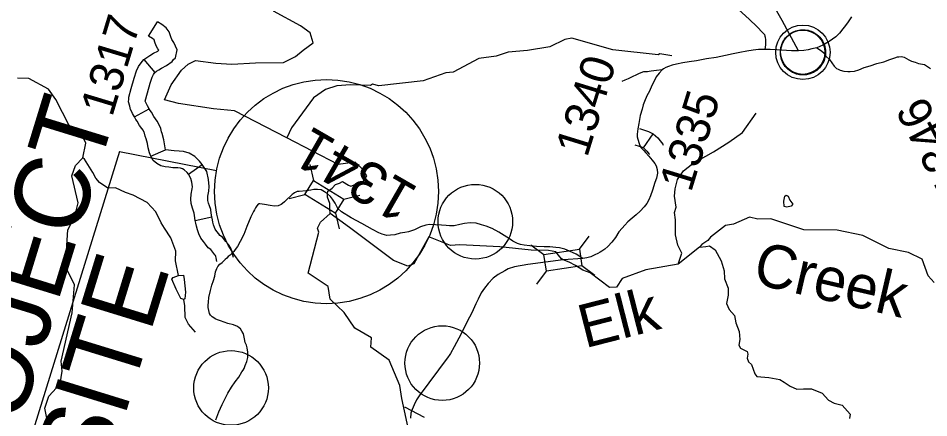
# Model space of a CAD drawing. Extents: x 1347947 to 1350662, y 1027710 to 1030532.
# Drawn here: x 1348130.6 to 1348252.2, y 1028877.9 to 1028931.2 of the extents above; entities that cross this region are included whole.
import ezdxf

# ---------------------------------------------------------------- set-up
doc = ezdxf.new("R2010")
doc.units = 0
for name, color, linetype in [('Default', 7, 'Continuous'), ('Prop Leader Line Light', 7, 'Continuous'), ('Prop Leader Line Medium', 7, 'Continuous'), ('Sheet Data Field CELL', 7, 'Continuous')]:
    doc.layers.add(name, color=color, linetype=linetype)

msp = doc.modelspace()

# ---------------------------------------------------------------- linework, layer by layer
at = {"layer": 'Default'}
for p, q in [((1348147.96, 1028928.84), (1348149.17, 1028930.74)), ((1348147.36, 1028925.69), (1348148.82, 1028923.97)), ((1348146.1, 1028918.05), (1348148.07, 1028919.14)), ((1348214.08, 1028913.91), (1348215.35, 1028915.8)), ((1348148.28, 1028912.8), (1348150.23, 1028913.64)), ((1348153.3, 1028910.4), (1348155.12, 1028911.72)), ((1348169.51, 1028911.7), (1348170.02, 1028909.58)), ((1348166.74, 1028907.17), (1348168.86, 1028907.68)), ((1348174.08, 1028907.08), (1348176.2, 1028907.59)), ((1348154.22, 1028904.25), (1348156.43, 1028904.7)), ((1348172.94, 1028905.22), (1348173.45, 1028903.11)), ((1348205.51, 1028900.39), (1348206.81, 1028902.14)), ((1348199.04, 1028900.99), (1348200.79, 1028899.69)), ((1348199.83, 1028895.74), (1348201.13, 1028897.49)), ((1348205.83, 1028898.24), (1348207.59, 1028896.94))]:
    msp.add_line(p, q, dxfattribs=at)
for points in [[(1348226.24, 1028932.88), (1348228.24, 1028931.02), (1348229.22, 1028930.12), (1348230.03, 1028929.25), (1348230.23, 1028929.03), (1348230.29, 1028928.82), (1348230.32, 1028928.7), (1348230.35, 1028928.33), (1348230.35, 1028927.65), (1348230.26, 1028927.04)], [(1348234.8, 1028926.88), (1348232.58, 1028930.89), (1348231.37, 1028933.07)], [(1348166.44, 1028915.24), (1348159.45, 1028918.86), (1348156.67, 1028919.11), (1348151.99, 1028919.83), (1348150.12, 1028920.32), (1348150.98, 1028922.32), (1348152.37, 1028924.29), (1348153.25, 1028925.09), (1348154.25, 1028925.58), (1348156.95, 1028925.21), (1348159.11, 1028925.08), (1348162.27, 1028925.27), (1348166, 1028925.3), (1348167.6, 1028926.11), (1348168.62, 1028926.97), (1348169.96, 1028927.94), (1348169.56, 1028929.26), (1348168.29, 1028930.21), (1348164.67, 1028932.15)], [(1348241.85, 1028931.38), (1348241.39, 1028930.73), (1348241.04, 1028930.24), (1348240.71, 1028929.79), (1348240.26, 1028929.22), (1348239.76, 1028928.73), (1348238.89, 1028928.09), (1348238.03, 1028927.63), (1348237.21, 1028927.25)], [(1348159.31, 1028899.29), (1348159.2, 1028899.76), (1348159.13, 1028900.06), (1348158.95, 1028900.56), (1348158.66, 1028901.02), (1348158.31, 1028901.43), (1348157.85, 1028902.01), (1348157.52, 1028902.25), (1348157.35, 1028902.45), (1348157.12, 1028902.77), (1348156.88, 1028903.08), (1348156.78, 1028903.28), (1348156.67, 1028903.65), (1348156.57, 1028904), (1348156.52, 1028904.3), (1348156.43, 1028904.7), (1348156.33, 1028905.21), (1348156.29, 1028905.68), (1348156.1, 1028906.2), (1348156, 1028906.53), (1348155.9, 1028906.88), (1348155.89, 1028907.09), (1348155.91, 1028907.46), (1348156.05, 1028908.13), (1348156.09, 1028908.76), (1348156, 1028909.72), (1348155.75, 1028910.75), (1348155.12, 1028911.72), (1348154.79, 1028912.13), (1348154.15, 1028912.77), (1348153.41, 1028913.23), (1348152.66, 1028913.42), (1348152.05, 1028913.49), (1348151.39, 1028913.52), (1348150.23, 1028913.64), (1348150.04, 1028915.01), (1348149.78, 1028915.84), (1348149.7, 1028916.06), (1348149.62, 1028916.49), (1348149.42, 1028916.99), (1348149.12, 1028917.49), (1348148.9, 1028917.8), (1348148.69, 1028918.1), (1348148.36, 1028918.69), (1348148.21, 1028918.9), (1348148.07, 1028919.14), (1348147.86, 1028919.54), (1348147.77, 1028919.72), (1348147.55, 1028920.16), (1348147.84, 1028921.25), (1348148.2, 1028922.54), (1348148.48, 1028923.36), (1348148.63, 1028923.69), (1348148.82, 1028923.97), (1348149.05, 1028924.14), (1348149.34, 1028924.35), (1348149.72, 1028924.55), (1348150.4, 1028924.92), (1348151.12, 1028925.44), (1348151.32, 1028925.69), (1348151.57, 1028925.94), (1348151.79, 1028926.99), (1348151.36, 1028927.97), (1348151.08, 1028928.36), (1348150.96, 1028928.72), (1348150.75, 1028929.38), (1348150.33, 1028929.94), (1348149.77, 1028930.36), (1348149.17, 1028930.74)], [(1348157.12, 1028898.78), (1348157.01, 1028899.24), (1348156.97, 1028899.42), (1348156.92, 1028899.56), (1348156.85, 1028899.67), (1348156.57, 1028900), (1348156.28, 1028900.37), (1348155.95, 1028900.6), (1348155.58, 1028901.07), (1348155.31, 1028901.42), (1348154.96, 1028901.89), (1348154.68, 1028902.45), (1348154.51, 1028903.01), (1348154.37, 1028903.49), (1348154.31, 1028903.86), (1348154.22, 1028904.25), (1348154.1, 1028904.91), (1348154.08, 1028905.2), (1348153.97, 1028905.47), (1348153.85, 1028905.87), (1348153.66, 1028906.51), (1348153.63, 1028907.1), (1348153.67, 1028907.76), (1348153.82, 1028908.45), (1348153.84, 1028908.73), (1348153.78, 1028909.34), (1348153.65, 1028909.85), (1348153.3, 1028910.4), (1348153.12, 1028910.62), (1348152.73, 1028911), (1348152.52, 1028911.14), (1348152.26, 1028911.2), (1348151.87, 1028911.25), (1348151.23, 1028911.27), (1348150.68, 1028911.33), (1348150.21, 1028911.4), (1348149.62, 1028911.52), (1348149.08, 1028911.85), (1348148.61, 1028912.25), (1348148.28, 1028912.8), (1348148.09, 1028913.27), (1348147.92, 1028913.94), (1348147.84, 1028914.52), (1348147.65, 1028915.13), (1348147.52, 1028915.48), (1348147.45, 1028915.86), (1348147.4, 1028915.99), (1348147.24, 1028916.27), (1348147.07, 1028916.5), (1348146.79, 1028916.89), (1348146.45, 1028917.49), (1348146.3, 1028917.7), (1348146.1, 1028918.05), (1348145.85, 1028918.52), (1348145.75, 1028918.73), (1348145.59, 1028919.05), (1348145.47, 1028919.47), (1348145.31, 1028920.05), (1348145.35, 1028920.41), (1348145.37, 1028920.69), (1348145.67, 1028921.83), (1348146.04, 1028923.21), (1348146.39, 1028924.21), (1348146.66, 1028924.79), (1348146.99, 1028925.28), (1348147.36, 1028925.69), (1348147.74, 1028925.97), (1348148.16, 1028926.26), (1348148.65, 1028926.53), (1348149.2, 1028926.82), (1348149.34, 1028926.93), (1348149.2, 1028927.12), (1348148.98, 1028927.53), (1348148.82, 1028928.04), (1348148.73, 1028928.33), (1348148.49, 1028928.5), (1348147.96, 1028928.84)], [(1348217.85, 1028926.18), (1348216.24, 1028926.48), (1348216.02, 1028926.31), (1348209.97, 1028926.99), (1348204.5, 1028928.56), (1348203.57, 1028928.37), (1348201.55, 1028927.38), (1348198.57, 1028926.89), (1348196.02, 1028926.68), (1348194.4, 1028926.15), (1348192.09, 1028925.85), (1348188.64, 1028924), (1348187.67, 1028923.92), (1348184.66, 1028922.84), (1348178.72, 1028922.2), (1348177.89, 1028922.41), (1348177.63, 1028922.25), (1348174.95, 1028922.33), (1348173.14, 1028922.2), (1348171.6, 1028921.72), (1348170, 1028920.59), (1348167.07, 1028916.59), (1348166.44, 1028915.24)], [(1348230.26, 1028927.04), (1348229.44, 1028927.02), (1348228.74, 1028926.93), (1348227.88, 1028926.8), (1348226.96, 1028926.63), (1348226.06, 1028926.44), (1348225.03, 1028926.23), (1348223.79, 1028925.99), (1348222.51, 1028925.78), (1348221.14, 1028925.54), (1348220.16, 1028925.4), (1348219.33, 1028925.24), (1348218.5, 1028925.08), (1348217.9, 1028924.96), (1348217.4, 1028924.79), (1348217.05, 1028924.66), (1348216.74, 1028924.48), (1348216.57, 1028924.34)], [(1348234.8, 1028926.88), (1348233.83, 1028926.85), (1348231.88, 1028926.98), (1348231, 1028927.04), (1348230.26, 1028927.04)], [(1348237.21, 1028927.25), (1348236.55, 1028927.11), (1348236.08, 1028927.01), (1348235.5, 1028926.9), (1348234.8, 1028926.88)], [(1348237.21, 1028927.25), (1348237.87, 1028926.85), (1348238.19, 1028926.53), (1348238.45, 1028926.16), (1348238.91, 1028925.69), (1348239.21, 1028925.27), (1348239.54, 1028924.82), (1348239.85, 1028924.51), (1348240.06, 1028924.41), (1348240.35, 1028924.29), (1348240.82, 1028924.17), (1348241.38, 1028924.12), (1348241.68, 1028924.11), (1348242.25, 1028924.14), (1348242.82, 1028924.33), (1348243.56, 1028924.63), (1348244.34, 1028924.88), (1348245.26, 1028925.16), (1348246.16, 1028925.41), (1348246.97, 1028925.72), (1348247.66, 1028925.95), (1348248, 1028926.04), (1348248.17, 1028926.07), (1348248.52, 1028926.11), (1348248.87, 1028926.01), (1348249.2, 1028925.85), (1348249.52, 1028925.64), (1348249.86, 1028925.48), (1348250.38, 1028925.33), (1348250.8, 1028925.18), (1348251.59, 1028925.02), (1348252.41, 1028924.5)], [(1348216.57, 1028924.34), (1348215.8, 1028924.24), (1348215.11, 1028924.13), (1348214.84, 1028924.11), (1348214.62, 1028924.08), (1348214.09, 1028924.04), (1348213.51, 1028923.86), (1348213.14, 1028923.64), (1348212.55, 1028923.39), (1348212.01, 1028923.13), (1348211.6, 1028922.95), (1348211.19, 1028922.77)], [(1348216.57, 1028924.34), (1348216.19, 1028923.89), (1348215.79, 1028923.38), (1348215.53, 1028922.91), (1348215.2, 1028922.23), (1348214.88, 1028921.47), (1348214.54, 1028920.86), (1348214.21, 1028920.12), (1348214.04, 1028919.65), (1348213.89, 1028919.08), (1348213.63, 1028918.23), (1348213.44, 1028917.15), (1348213.32, 1028916.44), (1348213.24, 1028915.76), (1348213.23, 1028915.41)], [(1348134.7, 1028876.27), (1348134.12, 1028879.19), (1348134.68, 1028880.8), (1348136.17, 1028882.45), (1348136.43, 1028884.15), (1348136.32, 1028885.46), (1348137.8, 1028891.92), (1348138.09, 1028895.64), (1348136.9, 1028898.1), (1348137.18, 1028903.01), (1348138.13, 1028904.8), (1348138.59, 1028906.59), (1348137.74, 1028910.21), (1348138.21, 1028911.57), (1348139.2, 1028912.6), (1348139.62, 1028914.56), (1348139.01, 1028915.79), (1348137.36, 1028916.89), (1348135.6, 1028920.38), (1348134.63, 1028921.75), (1348131.99, 1028923.18), (1348130.49, 1028923.2)], [(1348218.69, 1028898.43), (1348219.19, 1028899.87), (1348218.67, 1028900.93), (1348218.34, 1028902.31), (1348218.34, 1028904.31), (1348218.22, 1028905.31), (1348218.46, 1028906), (1348218.22, 1028907.47), (1348218.31, 1028908.46), (1348218.64, 1028909.71), (1348219.43, 1028910.86), (1348220.65, 1028911.82), (1348223.44, 1028913.39), (1348225.47, 1028914.66), (1348227.32, 1028915.97), (1348229.12, 1028918.56)], [(1348213.23, 1028915.41), (1348213.46, 1028914.64), (1348213.54, 1028914.35), (1348213.74, 1028913.99), (1348214.11, 1028913.58), (1348214.38, 1028913.26), (1348214.77, 1028912.83), (1348215.25, 1028912.3), (1348215.59, 1028911.84), (1348215.76, 1028911.51), (1348215.89, 1028911.03), (1348215.93, 1028910.54), (1348215.8, 1028909.87), (1348215.57, 1028909.3), (1348215.26, 1028908.29), (1348215, 1028907.54), (1348214.8, 1028907), (1348214.52, 1028906.49), (1348214.18, 1028906.05), (1348213.64, 1028905.49), (1348213.11, 1028904.98), (1348212.56, 1028904.56), (1348212, 1028904.06), (1348211.58, 1028903.6), (1348211.22, 1028903.23), (1348210.8, 1028902.73), (1348210.35, 1028901.98), (1348209.84, 1028901.35), (1348209.3, 1028900.75), (1348208.92, 1028900.41), (1348208.5, 1028900.16), (1348208.28, 1028900.03), (1348207.98, 1028899.83), (1348207.57, 1028899.67), (1348207.31, 1028899.53), (1348207.04, 1028899.4), (1348206.53, 1028899.27), (1348205.96, 1028899.16)], [(1348213.53, 1028916.49), (1348214.23, 1028916.3), (1348214.73, 1028916.1), (1348215.35, 1028915.8), (1348215.98, 1028915.24), (1348216.29, 1028914.85), (1348216.64, 1028914.4), (1348216.71, 1028914.3)], [(1348171.86, 1028907.78), (1348171.94, 1028908.13), (1348172.49, 1028908.55), (1348172.96, 1028909.03), (1348173.48, 1028909.23), (1348173.88, 1028909.42), (1348174.68, 1028908.95), (1348174.98, 1028908.83), (1348176.68, 1028909.47), (1348177.12, 1028910.18), (1348176.55, 1028911.07), (1348175.57, 1028912), (1348173.31, 1028911.72), (1348166.44, 1028915.24)], [(1348212.93, 1028914.32), (1348213.51, 1028914.16), (1348213.82, 1028914.04), (1348214.08, 1028913.91), (1348214.35, 1028913.67), (1348214.52, 1028913.46), (1348214.82, 1028913.08), (1348214.85, 1028913.02)], [(1348150.97, 1028901.93), (1348150.12, 1028903.19), (1348149.68, 1028903.91), (1348148.94, 1028905.41), (1348147.78, 1028906.64), (1348145.93, 1028907.59), (1348144.92, 1028907.95), (1348143.57, 1028908.58), (1348142.53, 1028908.54), (1348141.41, 1028909.3), (1348140.96, 1028909.86), (1348140.56, 1028910.64), (1348139.44, 1028912.41), (1348139.2, 1028912.6)], [(1348171.86, 1028907.78), (1348171.47, 1028908.06), (1348171.05, 1028908.32), (1348170.53, 1028908.38), (1348170.06, 1028908.36), (1348169.66, 1028908.28), (1348169.02, 1028908.21), (1348168.11, 1028908.12), (1348167.82, 1028908.1), (1348167.48, 1028907.91), (1348167.31, 1028907.81), (1348167.16, 1028907.68), (1348166.92, 1028907.46), (1348166.55, 1028907.13), (1348166.14, 1028906.72), (1348165.89, 1028906.51), (1348165.7, 1028906.36), (1348165.29, 1028906.17), (1348164.79, 1028906.16), (1348164.23, 1028906.24), (1348163.47, 1028906.36), (1348162.86, 1028906.45), (1348162.73, 1028906.45), (1348162.62, 1028906.4), (1348162.46, 1028906.18), (1348162.28, 1028905.92), (1348162.11, 1028905.64), (1348161.98, 1028905.44), (1348161.65, 1028904.72), (1348161.12, 1028903.44), (1348160.71, 1028902.35), (1348160.23, 1028901.41), (1348159.87, 1028900.78), (1348159.57, 1028900.35), (1348159.35, 1028900.11), (1348158.86, 1028899.63), (1348158.63, 1028899.42), (1348158.42, 1028899.2), (1348158.22, 1028899.03)], [(1348172.25, 1028905.18), (1348172.19, 1028905.79), (1348172.19, 1028906.51), (1348171.87, 1028907.35), (1348171.86, 1028907.78)], [(1348205.96, 1028899.16), (1348205.07, 1028899.76), (1348204.18, 1028900.16), (1348203.57, 1028900.42), (1348202.85, 1028900.58), (1348202.38, 1028900.62), (1348201.55, 1028900.72), (1348200.8, 1028900.7), (1348199.78, 1028900.76), (1348198.92, 1028900.85), (1348198.15, 1028900.95), (1348197.66, 1028901.01), (1348197.26, 1028901.15), (1348196.65, 1028901.48), (1348196.2, 1028901.78), (1348195.49, 1028902.24), (1348194.76, 1028902.69), (1348193.87, 1028903.18), (1348193.08, 1028903.48), (1348192.45, 1028903.66), (1348191.72, 1028903.86), (1348190.91, 1028903.92), (1348190.16, 1028903.84), (1348189.53, 1028903.68), (1348188.78, 1028903.54), (1348188.16, 1028903.51), (1348187.71, 1028903.55), (1348187.1, 1028903.59), (1348186.28, 1028903.64), (1348185.5, 1028903.72), (1348184.99, 1028903.59), (1348184.31, 1028903.4), (1348183.51, 1028903.01), (1348182.68, 1028902.74), (1348182.2, 1028902.62), (1348181.6, 1028902.55), (1348180.85, 1028902.31), (1348180.31, 1028902.26), (1348179.81, 1028902.21), (1348179.2, 1028902.39), (1348178.74, 1028902.61), (1348177.87, 1028903.03), (1348176.46, 1028903.83), (1348175.03, 1028904.61), (1348173.75, 1028905.39), (1348173.26, 1028905.85), (1348172.92, 1028906.54), (1348172.56, 1028907.1), (1348172.26, 1028907.45), (1348171.86, 1028907.78)], [(1348233.78, 1028906.16), (1348233.23, 1028905.99), (1348232.87, 1028906.11), (1348232.84, 1028906.8), (1348232.97, 1028907.46), (1348233.13, 1028907.61), (1348233.38, 1028907.46), (1348233.6, 1028906.94), (1348234.03, 1028906.42), (1348233.78, 1028906.16)], [(1348181.17, 1028864.6), (1348181.41, 1028868.13), (1348182.01, 1028870.15), (1348183.11, 1028874.69), (1348182.5, 1028877.18), (1348181.79, 1028880.51), (1348181.55, 1028882.21), (1348180.13, 1028885.6), (1348177.67, 1028887.36), (1348177.77, 1028888.57), (1348175.54, 1028889.88), (1348174.09, 1028891.94), (1348172.25, 1028893.72), (1348171.98, 1028895.42), (1348169.29, 1028897.21), (1348170.72, 1028902.66), (1348170.54, 1028903.22), (1348170.93, 1028904.03), (1348172.25, 1028905.18)], [(1348203.36, 1028898.97), (1348203.11, 1028899.13), (1348202.74, 1028899.62), (1348202.39, 1028900.05), (1348201.38, 1028900.21), (1348199.08, 1028900.28), (1348194.9, 1028900.71), (1348189.57, 1028900.98), (1348188.29, 1028900.88), (1348185.39, 1028902.06), (1348183.43, 1028898.46), (1348182.62, 1028898.15), (1348180.68, 1028898.91), (1348174.83, 1028903.3), (1348172.25, 1028905.18)], [(1348252.9, 1028895.98), (1348252.1, 1028896.85), (1348251.28, 1028899.09), (1348249.48, 1028899.98), (1348246.85, 1028900.48), (1348243.37, 1028902.21), (1348239.96, 1028902.94), (1348235.5, 1028903.01), (1348231.08, 1028904.46), (1348229.35, 1028904.39), (1348228.25, 1028904.69), (1348226.08, 1028903.75), (1348225.03, 1028903.56), (1348223.02, 1028902.01)], [(1348223.02, 1028902.01), (1348222.65, 1028901.56), (1348221.89, 1028901.04), (1348221.55, 1028900.66), (1348218.69, 1028898.43), (1348214.4, 1028897.66), (1348211.24, 1028896.49), (1348210.47, 1028895.36), (1348209.55, 1028895.29), (1348206.94, 1028897.24), (1348205.99, 1028897.59), (1348205, 1028898.25), (1348204.14, 1028898.69), (1348203.36, 1028898.97)], [(1348151.96, 1028896.9), (1348151.58, 1028898.86), (1348151.62, 1028900.13), (1348150.97, 1028901.93)], [(1348221.55, 1028900.66), (1348222.4, 1028900.75), (1348222.88, 1028900.84), (1348223.67, 1028900.3), (1348224.43, 1028898.87), (1348224.86, 1028897.54), (1348224.9, 1028896.47), (1348225.38, 1028895.22), (1348225.4, 1028894.29), (1348225.16, 1028893.15), (1348225.5, 1028892.36), (1348226.23, 1028891.55), (1348226.4, 1028890.58), (1348226.86, 1028889.44), (1348226.96, 1028888.38), (1348226.83, 1028887.61), (1348227.05, 1028887.19), (1348227.92, 1028886.74), (1348228.02, 1028886.4), (1348227.93, 1028885.86), (1348228.08, 1028885.4), (1348228.49, 1028885.01), (1348228.93, 1028883.77), (1348229.22, 1028883.43), (1348230.8, 1028883.28), (1348232.28, 1028883.01), (1348232.87, 1028882.66), (1348233.66, 1028882.12), (1348234.55, 1028881.75), (1348235.44, 1028881.8), (1348236.5, 1028881.8), (1348237.92, 1028881.2), (1348238.77, 1028880.25), (1348239.56, 1028879.87), (1348240.59, 1028879.61), (1348241.69, 1028878.39), (1348241.59, 1028877.81)], [(1348156.96, 1028877.66), (1348157.37, 1028878.72), (1348157.81, 1028879.71), (1348158.22, 1028880.49), (1348158.58, 1028881.21), (1348159.05, 1028882.01), (1348159.55, 1028882.71), (1348160.06, 1028883.33), (1348160.46, 1028884.06), (1348160.62, 1028884.29), (1348160.74, 1028884.51), (1348160.9, 1028884.89), (1348161.1, 1028885.41), (1348161.24, 1028885.98), (1348161.26, 1028886.42), (1348161.24, 1028886.69), (1348161.16, 1028887.27), (1348161.04, 1028887.61), (1348160.89, 1028887.97), (1348160.78, 1028888.46), (1348160.64, 1028889.1), (1348160.46, 1028889.49), (1348160.24, 1028889.79), (1348160.1, 1028889.9), (1348159.85, 1028890.08), (1348159.31, 1028890.31), (1348158.55, 1028890.5), (1348158.08, 1028890.66), (1348157.6, 1028890.83), (1348157.2, 1028890.99), (1348156.89, 1028891.13), (1348156.68, 1028891.24), (1348156.49, 1028891.38), (1348156.26, 1028891.62), (1348156.12, 1028891.85), (1348156.01, 1028892.24), (1348155.95, 1028892.61), (1348155.95, 1028892.95), (1348155.98, 1028893.35), (1348156.05, 1028893.95), (1348156.27, 1028894.89), (1348156.45, 1028895.62), (1348156.65, 1028896.23), (1348156.82, 1028896.81), (1348156.92, 1028897.4), (1348157.09, 1028897.83), (1348157.22, 1028898.09), (1348157.51, 1028898.4), (1348157.82, 1028898.64), (1348158.22, 1028899.03)], [(1348203.36, 1028898.97), (1348198.61, 1028898.35), (1348196.84, 1028898.04), (1348196.01, 1028897.78), (1348195.54, 1028897.53), (1348194.67, 1028897.02), (1348194, 1028896.54), (1348193.33, 1028895.83), (1348192.84, 1028895.2), (1348192.38, 1028894.58), (1348191.99, 1028893.73), (1348191.69, 1028893.1), (1348191.16, 1028891.91), (1348190.55, 1028890.78), (1348189.98, 1028889.63), (1348189.42, 1028888.52), (1348188.8, 1028887.39), (1348188.3, 1028886.5), (1348188.12, 1028886.22), (1348188, 1028886.04), (1348184.12, 1028880.85), (1348183.77, 1028880.32), (1348183.45, 1028879.65), (1348183.17, 1028879.02), (1348183, 1028878.53), (1348182.95, 1028877.85)], [(1348205.96, 1028899.16), (1348203.36, 1028898.97)], [(1348152.71, 1028893.68), (1348152.31, 1028893.82), (1348151.66, 1028895.06), (1348151.07, 1028896.39), (1348151.25, 1028896.63), (1348151.96, 1028896.9)], [(1348151.96, 1028896.9), (1348152.65, 1028896.96), (1348152.75, 1028896.35), (1348152.91, 1028894.67), (1348152.81, 1028893.78), (1348152.71, 1028893.68)], [(1348154.27, 1028889.34), (1348153.31, 1028890.4), (1348152.86, 1028891.28), (1348152.83, 1028892.86), (1348152.71, 1028893.68)], [(1348182.15, 1028879.37), (1348184.81, 1028878.01)]]:
    msp.add_lwpolyline(points, dxfattribs=at)
for points in [[(1348233.98, 1028923.98), (1348233.78, 1028924.09), (1348233.56, 1028924.23), (1348233.34, 1028924.42), (1348233.16, 1028924.6), (1348232.99, 1028924.79), (1348232.85, 1028924.99), (1348232.74, 1028925.18), (1348232.62, 1028925.41), (1348232.52, 1028925.66), (1348232.45, 1028925.91), (1348232.4, 1028926.12), (1348232.37, 1028926.33), (1348232.36, 1028926.56), (1348232.36, 1028926.79), (1348232.37, 1028926.96), (1348232.4, 1028927.15), (1348232.42, 1028927.3), (1348232.49, 1028927.54), (1348232.54, 1028927.7), (1348232.62, 1028927.91), (1348232.7, 1028928.08), (1348232.8, 1028928.24), (1348232.91, 1028928.41), (1348233.04, 1028928.58), (1348233.23, 1028928.79), (1348233.43, 1028928.97), (1348233.62, 1028929.12), (1348233.83, 1028929.26), (1348233.98, 1028929.34), (1348234.19, 1028929.44), (1348234.41, 1028929.52), (1348234.62, 1028929.58), (1348234.84, 1028929.64), (1348235.05, 1028929.67), (1348235.26, 1028929.68), (1348235.46, 1028929.68), (1348235.65, 1028929.67), (1348235.88, 1028929.64), (1348236.06, 1028929.6), (1348236.28, 1028929.54), (1348236.49, 1028929.47), (1348236.69, 1028929.38), (1348236.88, 1028929.28), (1348237.09, 1028929.15), (1348237.28, 1028929.01), (1348237.44, 1028928.86), (1348237.62, 1028928.68), (1348237.78, 1028928.49), (1348237.91, 1028928.31), (1348238.03, 1028928.1), (1348238.15, 1028927.85), (1348238.24, 1028927.61), (1348238.31, 1028927.39), (1348238.35, 1028927.2), (1348238.38, 1028926.91), (1348238.4, 1028926.62), (1348238.38, 1028926.39), (1348238.35, 1028926.13), (1348238.31, 1028925.96), (1348238.27, 1028925.79), (1348238.2, 1028925.59), (1348238.14, 1028925.44), (1348238.04, 1028925.24), (1348237.92, 1028925.04), (1348237.82, 1028924.89), (1348237.69, 1028924.72), (1348237.56, 1028924.58), (1348237.44, 1028924.46), (1348237.21, 1028924.26), (1348236.98, 1028924.1), (1348236.76, 1028923.98), (1348236.53, 1028923.87), (1348236.35, 1028923.8), (1348236.16, 1028923.74), (1348235.85, 1028923.68), (1348235.7, 1028923.66), (1348235.53, 1028923.64), (1348235.2, 1028923.65), (1348234.93, 1028923.67), (1348234.73, 1028923.71), (1348234.49, 1028923.77), (1348234.32, 1028923.83), (1348234.09, 1028923.93)], [(1348170.02, 1028909.58), (1348174.08, 1028907.09), (1348172.92, 1028905.19), (1348168.86, 1028907.68)], [(1348200.79, 1028899.69), (1348205.51, 1028900.4), (1348205.84, 1028898.2), (1348201.13, 1028897.49)]]:
    msp.add_lwpolyline(points, close=True, dxfattribs=at)
for centre, radius in [((1348235.36, 1028926.67), 3.63), ((1348235.34, 1028926.67), 2.95)]:
    msp.add_circle(centre, radius, dxfattribs=at)
at = {"layer": 'Prop Leader Line Light'}
for centre in [(1348191.62, 1028904.07), (1348191.62, 1028904.07), (1348187.2, 1028885.21), (1348187.2, 1028885.21), (1348159, 1028881.9), (1348159, 1028881.9)]:
    msp.add_circle(centre, 4.98, dxfattribs=at)
at = {"layer": 'Prop Leader Line Medium'}
for q in [(1348126.44, 1028856.54), (1348157.07, 1028910.92)]:
    msp.add_line((1348144.09, 1028913.43), q, dxfattribs=at)
msp.add_circle((1348171.75, 1028908.09), 14.95, dxfattribs=at)
msp.add_circle((1348171.75, 1028908.09), 14.95, dxfattribs=at)

# ---------------------------------------------------------------- texts
at = {"layer": 'Default'}
for s, rotation, p in [('Creek', 346.9577, (1348228.48, 1028895.88)), ('Elk', 14.3479, (1348206.25, 1028887.17))]:
    msp.add_text(s, height=5.771, rotation=rotation, dxfattribs=at).set_placement(p)
at = {"layer": 'Prop Leader Line Light'}
for s, height, rotation, p in [('1317', 4.5, 73.1949, (1348143.12, 1028917.93)), ('1340', 4.5, 72.8834, (1348206.55, 1028912.53)), ('1335', 4.5, 72.8834, (1348220.42, 1028907.87)), ('1346', 4.5, 117.6348, (1348257.83, 1028909.18)), ('1341', 5.625, 150.0492, (1348184.21, 1028908.51))]:
    msp.add_text(s, height=height, rotation=rotation, dxfattribs=at).set_placement(p)
at = {"layer": 'Sheet Data Field CELL'}
for s, p in [('PROJECT', (1348125.32, 1028859.01)), ('SITE', (1348142.08, 1028869.24))]:
    msp.add_text(s, height=10, rotation=72.8834, dxfattribs=at).set_placement(p)

doc.saveas('drawing.dxf')
